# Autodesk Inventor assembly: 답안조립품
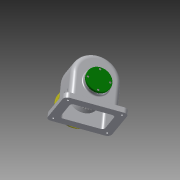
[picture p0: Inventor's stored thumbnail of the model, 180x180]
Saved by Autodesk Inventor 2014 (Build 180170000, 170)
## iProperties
Created: 2016-10
Part Number: 답안조립품
Document SubType Name: Assembly
Designer: SEC
Author: SEC
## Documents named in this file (15)
- C:\Documents and Settings\SEC\바탕 화면\답안조립품.iam
- C:\Documents and Settings\SEC\바탕 화면\본체.ipt
- C:\Documents and Settings\SEC\바탕 화면\461007V1014\축.ipt
- C:\Documents and Settings\SEC\바탕 화면\461007V1014\V-벨트풀리.ipt
- C:\Documents and Settings\SEC\바탕 화면\461007V1014\키 - 6 x 6 x 22.ipt
- C:\Documents and Settings\SEC\바탕 화면\461007V1014\키 - 5 x 5 x 18.ipt
- C:\Documents and Settings\SEC\바탕 화면\461007V1014\오일씰 28 40 8.ipt
- C:\Documents and Settings\SEC\바탕 화면\461007V1014\앞커버.ipt
- C:\Documents and Settings\SEC\바탕 화면\461007V1014\스퍼기어.ipt
- C:\Documents and Settings\SEC\바탕 화면\461007V1014\부시.ipt
- C:\Documents and Settings\SEC\바탕 화면\461007V1014\볼트 M3 x 10.ipt
- C:\Documents and Settings\SEC\바탕 화면\461007V1014\볼트 M3 x 8.ipt
- C:\Documents and Settings\SEC\바탕 화면\461007V1014\베어링 6203.ipt
- C:\Documents and Settings\SEC\바탕 화면\461007V1014\멈춤나사 - M4x10.ipt
- C:\Documents and Settings\SEC\바탕 화면\461007V1014\뒤커버.ipt
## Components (9 placed, 3 different names)
1. V-벨트풀리:1
2. ISO 4762 M3 x 10:1
3. ISO 4762 M3 x 8:1
4. ISO 4762 M3 x 10:2
5. ISO 4762 M3 x 8:2
6. ISO 4762 M3 x 10:3
7. ISO 4762 M3 x 8:3
8. ISO 4762 M3 x 10:4
9. ISO 4762 M3 x 8:4
